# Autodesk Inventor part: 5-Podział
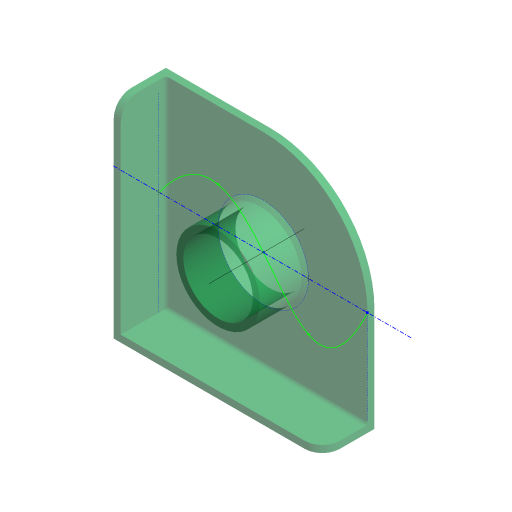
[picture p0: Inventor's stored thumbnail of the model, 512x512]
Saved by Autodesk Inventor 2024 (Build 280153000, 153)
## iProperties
Company: ATC
Shininess: 0.0
Length Units: 11269
Angle Units: 11279
Time Units: 11290
Mass Units: 11283
Length Display Precision: 3
Angle Display Precision: 2
Compacted: True
Created: 2023-03
Part Number: 5-Podział
Document SubType Name: Modeling
Designer: Andrzej Jaskulski
Material: Kurs-AJ
Density: 1 g/cm^3
Appearance: Przezroczyste - zielone 1
Checked By: A.J.
Engr Approved By: Andrzej Jaskulski
Mfg Approved By: Andrzej Jaskulski
Authority: A.J.
Density: 0.0
Volumn: 0.0
Area: 0.0
PropertySet Name: Model Information
Control State: 0
Master: False
Checked Out: False
Title: A.J.: Kurs R2024-MEP
Author: Andrzej Jaskulski
Revision Number: 1/24
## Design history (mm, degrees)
node "Extrusion1" dims "d1" = 15, "d2" = 0
node "Hole1" dims "d5" = 20, "d6" = 4, "d7" = 2, "d8" = 60 deg, "d9" = 8, "d10" = 118 deg
workaxis "Work Axis1"
node "Fillet1" dims "d12" = 5
node "Fillet2" dims "d13" = 30
node "Shell2" dims "d14" = 2
node "Fillet3" dims "d30" = 1
node "Chamfer1" dims "d31" = 1, "d32" = 1, "d35" = 45 deg
node "Pł.Podziału"
sketch "L.Podziału"
  geometry: L1 (57, 27)-(57, 0) reference; L2 (-16.172, 27)-(69.899, 27) reference; L3 (-3, 52)-(-3, -3) reference; A1 r 13 centre (27, 27) between (14, 27) and (40, 27) reference; 3 further points
  constraints: 4 point on line, 2 point on circle, 2 vertical alignment, 5 other
node "Bryła1"
node "Korpusy bryłowe"
node "Korpusy powierzchniowe"
sketch "Sketch1"
  geometry: L1 (0, 0)-(60, 0); L2 (60, 0)-(60, 60); L3 (60, 60)-(0, 60); L4 (0, 60)-(0, 0)
  constraints: 8 end point, 2 parallel, 2 perpendicular, 1 horizontal, 1 other
  dimensions: "d0" = 60 distance of L1.start L1.end
sketch "Sketch3"
  geometry: L1 (0, 0)-(60, 0) reference; L2 (0, 60)-(0, 0) reference; 1 further point
  dimensions: "d3" = 30 distance from line of L1 point (30, 30); "d4" = 30 distance from line of L2 point (30, 30)
other parameters: "d36" = 0
